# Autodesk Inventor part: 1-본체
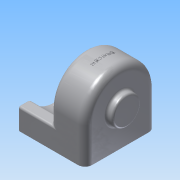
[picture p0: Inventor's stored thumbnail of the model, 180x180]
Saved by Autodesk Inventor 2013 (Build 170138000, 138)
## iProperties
Created: 2015-02
Part Number: 1-본체
Material: 알루미늄 6061
Document SubType Name: Modeling
Designer: Administrator
Density: 2.40731 g/cm^3
Mass: 559.928 g
Surface Area: 696.786 cm^2
Volume: 232.595 cm^3
Author: Administrator
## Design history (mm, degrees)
sketch "스케치1"
  geometry: L1 (25, -50)-(-25, -50); L2 (-25, -50)-(-25, 50); L3 (-25, 50)-(25, 50); L4 (25, 50)-(25, -50); L5 (25, -50)-(-25, 50); L6 (-25, -50)-(25, 50); 1 further point
  constraints: 12 end point, 2 midpoint, 2 parallel, 1 horizontal, 1 perpendicular
  dimensions: "d0" = 50 distance of L2.end L3.end; "d2" = 100 distance of L1.end L2.end
extrude "돌출1" new body sketch "스케치1" distance "d3" = 100; taper "d4" = 0 deg
fillet "모깎기1" dims "d5" = 50
sketch "스케치2"
  geometry: C1 r 25 at (50, 50); A1 r 50 centre (50, 50) between (50, 0) and (50, 100) reference; 1 further point
  constraints: 1 centre point, 1 coincident
  dimensions: "d7" = 50 diameter of C1
extrude "돌출2" join sketch "스케치2" distance "d9" = 10; taper "d10" = -20 deg
sketch "스케치3"
  geometry: C1 r 20 at (-50, 50); A1 r 50 centre (-50, 50) between (-50, 100) and (-50, 0) reference; 1 further point
  constraints: 1 centre point, 1 coincident
  dimensions: "d11" = 40 diameter of C1
extrude "돌출3" join sketch "스케치3" distance "d13" = 9; taper "d14" = 0 deg
node "작업 평면1"
sketch "스케치4"
  geometry: L1 (0, 100)-(50, 100) reference; L2 (0, 0)-(0, 100) reference; L3 (0, 0)-(50, 0) reference; L4 (0, 100)-(28, 100); L5 (30, 84.641)-(30, 100); L6 (28, 100)-(30, 100); L7 (30, 15.359)-(30, 0); L8 (0, 0)-(0, 100); L9 (30, 0)-(0, 0); A1 r 50 centre (50, 50) between (50, 0) and (50, 100) reference; A2 r 40 centre (50, 50) between (30, 84.641) and (30, 15.359); 1 further point
  constraints: 12 end point, 3 collinear, 3 point on line, 2 perpendicular, 2 point on circle, 1 centre point, 1 coincident
  dimensions: "d16" = 40 radius of A2; "d18" = 30 distance between parallel lines of L8 L5; "d19" = 30 distance between parallel lines of L2 L7
extrude "돌출4" join sketch "스케치4" stored distance "d20" = 9; taper "d21" = 0 deg
hole "구멍1" diameter "d24" = 20; stored, may be unused: countersink angle "d28" = 90 deg, drill point angle "d30" = 0 deg; dims "d25" = 6, "d26" = 28, "d27" = 10, "d29" = 14, "d38" = 10, "d39" = 10
sketch "스케치6"
  geometry: C1 r 14 at (0, 0) reference; C2 r 21.36 at (0, 0) reference; A1 r 18 centre (0, 0) between (18, 0) and (0, 18); 3 further points
  constraints: 4 point on circle, 2 horizontal alignment, 2 vertical alignment, 1 centre point, 1 coincident
  dimensions: "d40" = 36 diameter of A1
hole "구멍3" sketch "스케치6" at (18, 0), (0, 18), (-18, 0), (0, -18) diameter "d42" = 2.459; stored, may be unused: countersink angle "d46" = 90 deg, drill point angle "d48" = 118 deg; dims "d43" = 6, "d44" = 28, "d45" = 8, "d47" = 9
sketch "스케치7"
  geometry: L1 (70, 50)-(70, -50) reference; L2 (61, -41.75)-(28, -41.75); L3 (28, -41.75)-(28, 41.75); L4 (28, 41.75)-(61, 41.75); L5 (61, 41.75)-(61, -41.75); 7 further points
  constraints: 8 end point, 4 coincident, 2 midpoint, 2 parallel, 1 horizontal, 1 horizontal alignment, 1 perpendicular, 1 point on line
  dimensions: "d49" = 33 distance of L2.start L2.end; "d51" = 83.5 distance of L4.end L2.start; "d52" = 9 distance between parallel lines of L1 L5
hole "구멍4" sketch "스케치7" at (61, -41.75), (28, -41.75), (28, 41.75), (61, 41.75) diameter "d53" = 5.134; stored, may be unused: countersink angle "d57" = 90 deg, drill point angle "d59" = 118 deg; dims "d54" = 10, "d55" = 28, "d56" = 8, "d58" = 13
fillet "모깎기2" dims "d60" = 0.3
fillet "모깎기3" dims "d61" = 10
fillet "모깎기4" dims "d62" = 3
fillet "모깎기5" dims "d63" = 3
chamfer "모따기1" distance "d64" = 1; stored, may be unused: second distance "d65" = 2, angle "d66" = 45 deg
node "작업 평면2"
sketch "스케치8"
  geometry: L1 (37.5, 40)-(37.5, -40) reference; 3 further points
  constraints: 1 horizontal alignment, 1 midpoint, 1 other
  dimensions: "d67" = 25 distance from line of point (12.5, 0) L1
feature "엠보싱1" sketch "스케치8" dims "d0" = 50, "d2" = 100, "d68" = 0.5, "d69" = 0
fillet "모깎기7" dims "d71" = 3
fillet "모깎기8" dims "d72" = 3
node "작업 평면3"
sketch "스케치9"
  geometry: 1 further point
node "작업 평면5"
sketch "스케치11"
  geometry: L1 (0, 46)-(-50, 46); L2 (0, -46)-(-50, -46); L3 (-50, 47)-(-50, -47) reference; A1 r 50 centre (0, 0) between (0, -50) and (0, 50) reference; A2 r 46 centre (0, 0) between (0, -46) and (0, 46); 1 further point
  constraints: 4 end point, 2 point on circle, 2 point on line, 2 tangent, 1 centre point, 1 horizontal, 1 parallel
  dimensions: "d79" = 4 radial gap between concentric circles of A1 A2
extrude "돌출5" cut sketch "스케치11" stored distance "d80" = 42; taper "d81" = 0 deg
sketch "스케치12"
  geometry: A1 r 46 centre (0, 0) between (0, -46) and (0, 46) reference; 2 further points
  constraints: 1 coincident
hole "구멍5" sketch "스케치12" at (0, 0) diameter "d82" = 20; stored, may be unused: countersink angle "d86" = 90 deg, drill point angle "d88" = 0 deg; dims "d83" = 6, "d84" = 28, "d85" = 8, "d87" = 10
fillet "모깎기10" dims "d89" = 0.3
fillet "모깎기11" dims "d90" = 3
fillet "모깎기12" dims "d91" = 6
chamfer "모따기2" distance "d92" = 1; stored, may be unused: second distance "d93" = 2, angle "d94" = 45 deg
node "솔리드1"
other parameters: "d15" = 45, "d74" = 0
